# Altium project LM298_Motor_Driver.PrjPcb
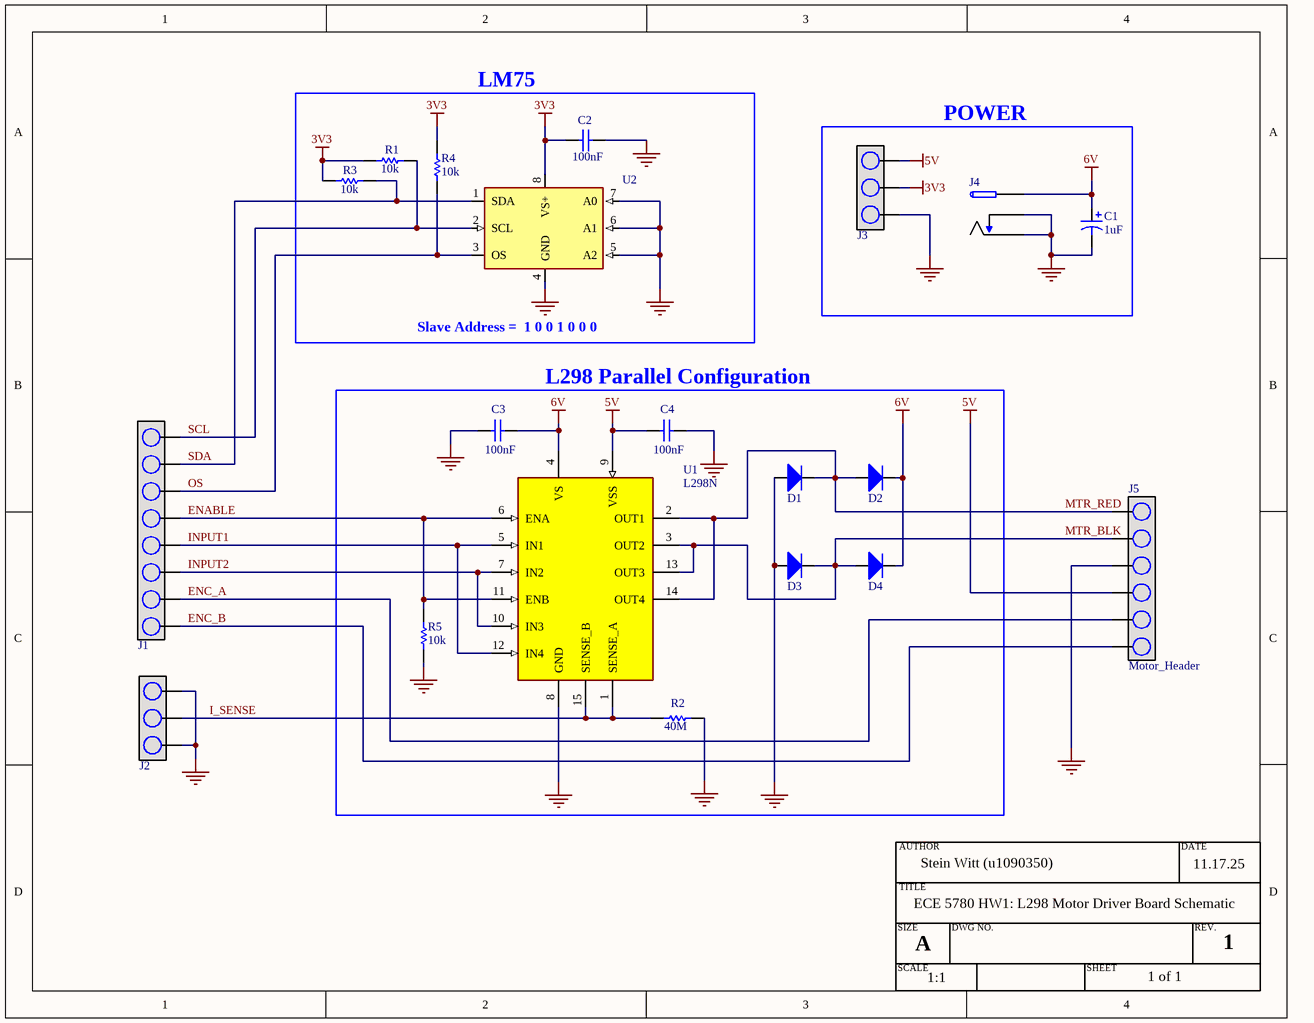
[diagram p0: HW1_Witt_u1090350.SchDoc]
1 sheet, 21 parts. Net scope: global (net labels, ports and power ports of the same name join across sheets).
Board file: L298_Board.PcbDoc

## Sheet HW1_Witt_u1090350.SchDoc
size A; SheetNumber: 1; SheetTotal: 1

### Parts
*  Title Block  (value not drawn)  (graphical)
C1  value 1uF  [CAP_TH_Radial_0511]  (hidden comment: REA010M2CBK-0511P)
C2  Capacitance: 100nF  [CAP_1206]  (hidden comment: C1206C104K5RAC7800)
C3  Capacitance: 100nF  [CAP_1206]  (hidden comment: C1206C104K5RAC7800)
C4  Capacitance: 100nF  [CAP_1206]  (hidden comment: C1206C104K5RAC7800)
D1  RS2AA R3G  [RS2AA]  (value not drawn)
D2  RS2AA R3G  [RS2AA]  (value not drawn)
D3  RS2AA R3G  [RS2AA]  (value not drawn)
D4  RS2AA R3G  [RS2AA]  (value not drawn)
J1  8 Pin Male Connector  [8 Pin THT Header]  (value not drawn)
J2  3 Pin 2.54mm Male Connector  [3 Pin THT Header]  (value not drawn)
J3  3 Pin 2.54mm Male Connector  [3 Pin THT Header]  (value not drawn)
J4  Barrel Jack  [GRAVITECH_CON-SOCJ-2155]  (value not drawn)
J5  Motor_Header  [6 Pin THT Header]
R1  value 10k  [RES_1206]  (hidden comment: RC1206JR-0710KL)
R2  value 40M  [RES_1206]  (hidden comment: RL1206FR-070R04L)
R3  value 10k  [RES_1206]  (hidden comment: RC1206JR-0710KL)
R4  value 10k  [RES_1206]  (hidden comment: RC1206JR-0710KL)
R5  value 10k  [RES_1206]  (hidden comment: RC1206JR-0710KL)
U1  L298N  [L298N]
U2  LM75AIMXNOPB  [SOIC8]  (value not drawn)

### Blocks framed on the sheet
LM75: C2 R1 R3 R4 U2
POWER: C1 J3 J4
L298 Parallel Configuration: C3 C4 D1-D4 R2 R5 U1

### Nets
3V3: C2.2 J3.2 R1.1 R3.1 R4.2 U2.8(VS+)
5V: C4.1 J3.3 J5.4 U1.9(VSS)
6V: C1.2(+) C3.2 D2.1(K) D4.1(K) J4.1(POS) U1.4(VS)
GND: C1.1(-) C2.1 C3.1 C4.2 D1.2(A) D3.2(A) J2.1 J2.3 J3.1 J4.2(NEG) J4.3(SW) J5.3 R2.1 R5.1 U1.8(GND) U2.4(GND) U2.5(A2) U2.6(A1) U2.7(A0)
ENABLE: J1.5 R5.2 U1.6(ENA) U1.11(ENB)
ENC_A: J1.2 J5.5
ENC_B: J1.1 J5.6
I_SENSE: J2.2 R2.2 U1.1(SENSE_A) U1.15(SENSE_B)
INPUT1: J1.4 U1.5(IN1) U1.12(IN4)
INPUT2: J1.3 U1.7(IN2) U1.10(IN3)
MTR_BLK: D3.1(K) D4.2(A) J5.2 U1.3(OUT2) U1.13(OUT3)
MTR_RED: D1.1(K) D2.2(A) J5.1 U1.2(OUT1) U1.14(OUT4)
OS: J1.6 R4.1 U2.3(OS)
SCL: J1.8 R1.2 U2.2(SCL)
SDA: J1.7 R3.2 U2.1(SDA)

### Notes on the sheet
- (near U2) Slave Address =  1 0 0 1 0 0 0
- ECE 5780 HW1: L298 Motor Driver Board Schematic
- Stein Witt (u1090350)
- 11.17.25
- (near *) A
- 1
- (near *) 1:1
- 1 of 1

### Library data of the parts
C1 = REA010M2CBK-0511P: Radial Leaded 160V 1.0uF 20% 5x11mm; Manufacturer: Lelon; Dielectric Material: Aluminium; Polarity: Polarized; Ripple Current: 20mA
C2-C4 = C1206C104K5RAC7800: 0.1 µF ±10% 50V Ceramic Capacitor X7R 1206 (3216 Metric)
D1-D4 = RS2AA R3G: Diode Fast Recovery Rectifier 50V 1.5A 2-Pin DO-214AC Plastic T/R; Manufacturer: Taiwan Semiconductor
J5 = 6 pin 2.54mm Male Connector
R1 R3-R5 = RC1206JR-0710KL: Res Thick Film 1206 10K Ohm 5% 1/4W ¦100ppm/¦C SMD Paper T/R; Manufacturer: Yageo; Temperature Coefficient: 100ppm/°C; Power Rating: 250mW; Voltage Rating: 200V
R2 = RL1206FR-070R04L: SMD Current Sense Resistor, 40 Milliohms, ± 1%, 250 mW, 1206 [3216 Metric], Thick Film; Manufacturer: Yageo; Power Rating: 250mW; Temperature Coefficient: 1200ppm/°C
U1 = L298N: Dual Full Bridge Motor Driver 15-Pin(15+Tab) MULTIWATT V Tube
U2 = LM75AIMXNOPB: No Description Available; Mfr_Name: Texas Instruments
